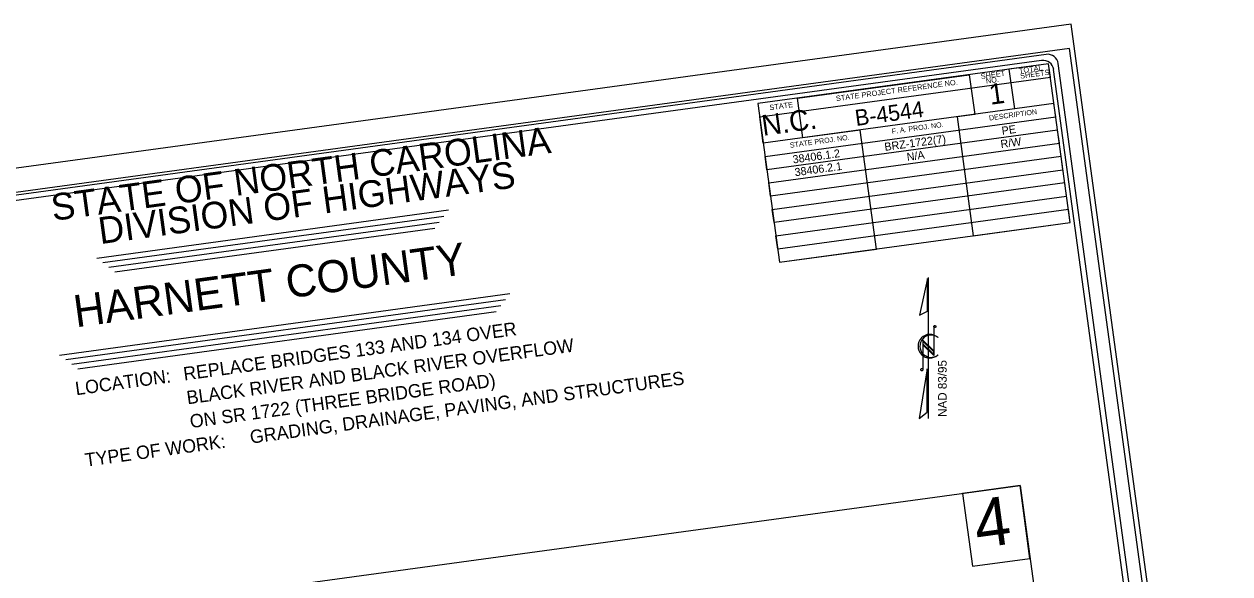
# Model space of a CAD drawing. Extents: x 2110583 to 2112764, y 580993 to 582575.
# Drawn here: x 2111407 to 2112764, y 581957 to 582575 of the extents above; entities that cross this region are included whole.
import ezdxf

# ---------------------------------------------------------------- set-up
doc = ezdxf.new("R2010")
doc.units = 0
for name, color, linetype in [('Default', 7, 'Continuous'), ('Sheet Data Field CELL', 7, 'Continuous'), ('Sheet North Arrow CELL', 7, 'Continuous'), ('Sheet Plan Layout CELL', 7, 'Continuous'), ('Sheet Plot Border Inside CELL', 7, 'Continuous'), ('Sheet Plot Border Outside CELL', 7, 'Continuous'), ('Sheet Title CELL', 7, 'Continuous')]:
    doc.layers.add(name, color=color, linetype=linetype)

msp = doc.modelspace()

# ---------------------------------------------------------------- linework, layer by layer
at = {"layer": 'Default'}
for points in [[(2111026.4, 581851.1), (2112527.7, 582056), (2112588.5, 581610.1), (2111087.3, 581405.2)], [(2112527.7, 582056), (2112462.9, 582047.1), (2112474.1, 581965.4), (2112538.8, 581974.2)]]:
    msp.add_lwpolyline(points, close=True, dxfattribs=at)
at = {"layer": 'Sheet North Arrow CELL'}
for p, q in [((2112424.6, 582131.3), (2112424.6, 582290.1)), ((2112430.6, 582234.9), (2112430.6, 582202.3)), ((2112430.6, 582207.4), (2112418.5, 582219.5)), ((2112418.5, 582219.5), (2112418.5, 582186.4)), ((2112430.6, 582206.2), (2112418.5, 582218.3)), ((2112418.5, 582218.3), (2112418.5, 582215.3)), ((2112430.6, 582203.2), (2112418.5, 582215.3)), ((2112418.5, 582215.3), (2112430.6, 582203.2)), ((2112430.6, 582202.3), (2112418.5, 582214.4)), ((2112435.1, 582222.7), (2112435.3, 582222.6)), ((2112430.6, 582203.2), (2112430.6, 582206.2))]:
    msp.add_line(p, q, dxfattribs=at)
for points in [[(2112423.5, 582288.8), (2112414.5, 582247.5), (2112423.5, 582252.1)], [(2112423.3, 582187.3), (2112414.4, 582131.3), (2112423.3, 582138.4)]]:
    msp.add_lwpolyline(points, close=True, dxfattribs=at)
for centre, major_axis, start_param, end_param in [((2112426.3, 582212.7), (4.6, -12.5), 2.056008, 6.673347), ((2112427.6, 582212.7), (4.3, -11.8), 2.147726, 6.60763)]:
    msp.add_ellipse(centre, major_axis=major_axis, ratio=0.999692, start_param=start_param, end_param=end_param, dxfattribs=at)
for centre in [(2112431.9, 582234.8), (2112417.2, 582186.3)]:
    msp.add_ellipse(centre, major_axis=(-0.44, 1.22), ratio=0.999692, dxfattribs=at)
at = {"layer": 'Sheet Plot Border Inside CELL'}
msp.add_lwpolyline([(2110773, 581021.7), (2112754.8, 581292.2), (2112583.5, 582547.3), (2110601.7, 582276.8)], close=True, dxfattribs=at)
at = {"layer": 'Sheet Plot Border Outside CELL'}
msp.add_lwpolyline([(2112585.2, 582574.7), (2110582.6, 582301.4), (2110761.2, 580992.9), (2112763.8, 581266.2)], close=True, dxfattribs=at)
at = {"layer": 'Sheet Title CELL'}
for p, q in [((2111489, 582311.8), (2111884.7, 582365.8)), ((2111495.7, 582306.6), (2111879.6, 582359)), ((2111502.5, 582301.5), (2111874.4, 582352.3)), ((2111509.3, 582296.4), (2111869.3, 582345.5)), ((2111447.3, 582202.8), (2111953.9, 582271.9)), ((2111454.1, 582197.6), (2111948.8, 582265.1)), ((2111460.9, 582192.5), (2111943.7, 582258.4)), ((2111467.6, 582187.4), (2111938.5, 582251.6))]:
    msp.add_line(p, q, dxfattribs=at)
for points in [[(2112557.2, 582540.6), (2110797.1, 582300.4)], [(2112552, 582533.8), (2110863.4, 582303.4)], [(2112257.1, 582307), (2112584.2, 582351.6), (2112582.1, 582366.5), (2112255.1, 582321.9), (2112253.1, 582336.7), (2112580.1, 582381.4), (2112578.1, 582396.2), (2112251.1, 582351.6), (2112249, 582366.5), (2112576, 582411.1), (2112574, 582426), (2112247, 582381.4), (2112245, 582396.2), (2112572, 582440.9), (2112570, 582455.7), (2112242.9, 582411.1), (2112240.9, 582425.9), (2112567.9, 582470.6), (2112565.9, 582485.5), (2112238.9, 582440.8), (2112234.8, 582470.6), (2112561.8, 582515.2), (2112559.8, 582530.1), (2112232.8, 582485.4), (2112257.1, 582307), (2112366.1, 582321.9), (2112347.9, 582455.7), (2112283.5, 582446.9), (2112277.4, 582491.5), (2112470.6, 582517.9), (2112476.7, 582473.3), (2112456.9, 582470.6), (2112475.1, 582336.8), (2112584.2, 582351.6), (2112559.8, 582530.1), (2112515.2, 582524), (2112521.3, 582479.4)], [(2112737.9, 581305.1), (2112570.7, 582530.3)], [(2112701.1, 581530.3), (2112565.5, 582523.6)]]:
    msp.add_lwpolyline(points, dxfattribs=at)
for centre in [(2112558.8, 582528.8), (2112553.7, 582522)]:
    msp.add_ellipse(centre, major_axis=(-1.6, 11.9), ratio=0.999692, start_param=4.712389, end_param=6.283185, dxfattribs=at)

# ---------------------------------------------------------------- texts
at = {"layer": 'Sheet Data Field CELL'}
for s, height, p in [('B-4544', 18.01, (2112343.3, 582460.2)), ('PE', 9, (2112507.7, 582450.3)), ('BRZ-1722(7)', 9.004, (2112375.8, 582432.2)), ('R/W', 9, (2112506.4, 582435.4)), ('38406.1.2', 9, (2112272.6, 582418.1)), ('N/A', 9, (2112400.9, 582420.9)), ('38406.2.1', 9, (2112274.8, 582403.7)), ('HARNETT COUNTY', 36.018, (2111465.6, 582233.8)), ('REPLACE BRIDGES 133 AND 134 OVER', 15.007, (2111587.5, 582174.1)), ('BLACK RIVER AND BLACK RIVER OVERFLOW', 15.007, (2111591.2, 582147.3)), ('ON SR 1722 (THREE BRIDGE ROAD)', 15.007, (2111594.8, 582120.6)), ('GRADING, DRAINAGE, PAVING, AND STRUCTURES', 15.007, (2111662.4, 582103.1))]:
    msp.add_text(s, height=height, rotation=7.771, dxfattribs=at).set_placement(p)
at = {"layer": 'Sheet North Arrow CELL'}
msp.add_text('NAD 83/95', height=9.77, rotation=90, dxfattribs=at).set_placement((2112445.2, 582133.2))
at = {"layer": 'Sheet Plan Layout CELL'}
msp.add_text('4', height=54.3, rotation=7.771, dxfattribs=at).set_placement((2112479.9, 581985.5))
at = {"layer": 'Sheet Title CELL'}
for s, height, p in [('TOTAL', 6, (2112526.9, 582519.3)), ('SHEET', 6, (2112483.9, 582513)), ('NO.', 6, (2112489.7, 582507.8)), ('SHEETS', 6, (2112528.2, 582513.4)), ('STATE PROJECT REFERENCE NO.', 6.003, (2112321, 582488.1)), ('1', 23.2, (2112494.4, 582484)), ('STATE', 6, (2112246.2, 582477.9)), ('N.C.', 23.23, (2112238.7, 582449.1)), ('DESCRIPTION', 5.763, (2112493.2, 582466.3)), ('STATE OF NORTH CAROLINA', 30.015, (2111439.9, 582353.5)), ('F. A. PROJ. NO.', 5.763, (2112383.7, 582451.3)), ('STATE PROJ. NO.', 5.763, (2112269.2, 582435.7)), ('DIVISION OF HIGHWAYS', 30.015, (2111493, 582327.4)), ('LOCATION: ', 15.01, (2111465.9, 582157.5)), ('TYPE OF WORK:', 15.007, (2111476.8, 582077.2))]:
    msp.add_text(s, height=height, rotation=7.771, dxfattribs=at).set_placement(p)

doc.saveas('drawing.dxf')
